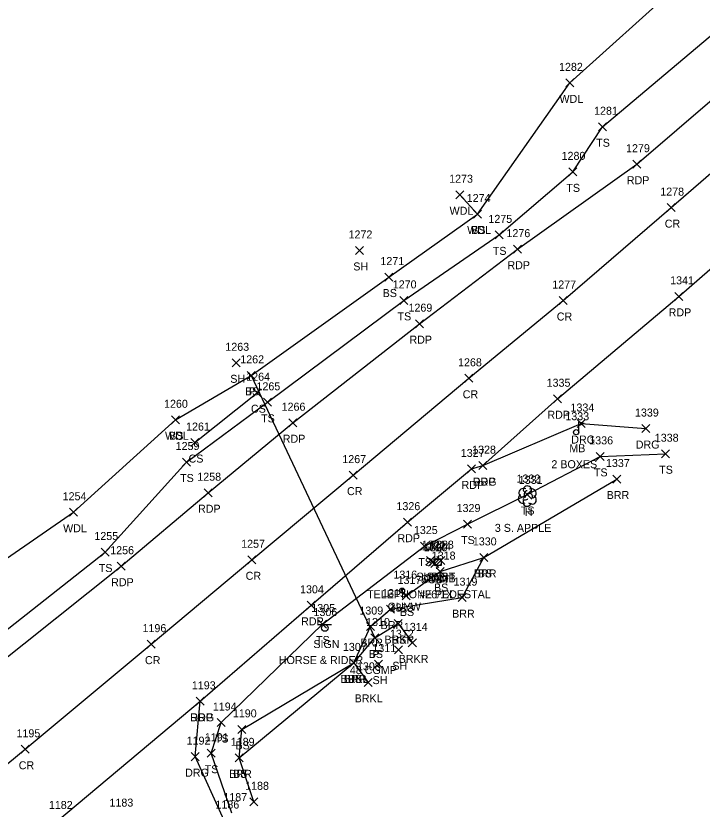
# Model space of a CAD drawing. Extents: x 1611797 to 1633212, y 298978 to 305475.
# Drawn here: x 1612409.8 to 1612581.3, y 300612.3 to 300810.6 of the extents above; entities that cross this region are included whole.
import ezdxf

# ---------------------------------------------------------------- set-up
doc = ezdxf.new("R2010")
doc.units = 0
for name, color, linetype in [('D_A', 7, 'Continuous'), ('D_I', 7, 'Continuous'), ('D_TIC', 7, 'Continuous'), ('DCP', 7, 'Continuous'), ('L_A', 7, 'Continuous'), ('L_C', 7, 'Continuous'), ('L_I', 7, 'Continuous'), ('L_TIC', 7, 'Continuous'), ('LABL', 7, 'Continuous'), ('LAWA', 7, 'Continuous'), ('LAWE', 7, 'Continuous'), ('LELB', 7, 'Continuous'), ('LMB', 7, 'Continuous'), ('LTD', 7, 'Continuous'), ('P_A', 7, 'Continuous'), ('P_I', 7, 'Continuous'), ('P_TIC', 7, 'Continuous'), ('PET', 7, 'Continuous'), ('PRC', 7, 'Continuous'), ('R_A', 7, 'Continuous'), ('R_I', 7, 'Continuous'), ('R_TIC', 7, 'Continuous'), ('RDG', 7, 'Continuous'), ('S_A', 7, 'Continuous'), ('S_C', 7, 'Continuous'), ('S_I', 7, 'Continuous'), ('SSGN', 7, 'Continuous'), ('U_A', 7, 'Continuous'), ('U_C', 7, 'Continuous'), ('U_I', 7, 'Continuous'), ('U_TIC', 7, 'Continuous'), ('UDEFAULT', 7, 'Continuous'), ('UP', 7, 'Continuous'), ('UPGW', 7, 'Continuous')]:
    doc.layers.add(name, color=color, linetype=linetype)

msp = doc.modelspace()

# ---------------------------------------------------------------- linework, layer by layer
at = {"layer": 'D_TIC'}
for points in [[(1612467.58, 300719.73), (1612469.58, 300721.73)], [(1612469.58, 300719.73), (1612467.58, 300721.73)], [(1612498.5, 300654.1), (1612500.5, 300656.1)], [(1612500.5, 300654.1), (1612498.5, 300656.1)]]:
    msp.add_lwpolyline(points, dxfattribs=at)
at = {"layer": 'DCP'}
msp.add_lwpolyline([(1612468.58, 300720.73), (1612499.5, 300655.1)], dxfattribs=at)
at = {"layer": 'L_TIC'}
for points in [[(1612547.19, 300792.82), (1612549.19, 300794.82)], [(1612549.19, 300792.82), (1612547.19, 300794.82)], [(1612555.39, 300781.85), (1612557.39, 300783.85)], [(1612557.39, 300781.85), (1612555.39, 300783.85)], [(1612547.92, 300770.58), (1612549.92, 300772.58)], [(1612549.92, 300770.58), (1612547.92, 300772.58)], [(1612519.74, 300764.86), (1612521.74, 300766.86)], [(1612521.74, 300764.86), (1612519.74, 300766.86)], [(1612524.12, 300760.04), (1612526.12, 300762.04)], [(1612526.12, 300760.04), (1612524.12, 300762.04)], [(1612524.12, 300760.04), (1612526.12, 300762.04)], [(1612526.12, 300760.04), (1612524.12, 300762.04)], [(1612529.55, 300754.83), (1612531.55, 300756.83)], [(1612531.55, 300754.83), (1612529.55, 300756.83)], [(1612494.6, 300750.94), (1612496.6, 300752.94)], [(1612496.6, 300750.94), (1612494.6, 300752.94)], [(1612501.99, 300744.29), (1612503.99, 300746.29)], [(1612503.99, 300744.29), (1612501.99, 300746.29)], [(1612505.73, 300738.46), (1612507.73, 300740.46)], [(1612507.73, 300738.46), (1612505.73, 300740.46)], [(1612463.85, 300722.86), (1612465.85, 300724.86)], [(1612465.85, 300722.86), (1612463.85, 300724.86)], [(1612467.58, 300719.73), (1612469.58, 300721.73)], [(1612469.58, 300719.73), (1612467.58, 300721.73)], [(1612469.07, 300715.39), (1612471.07, 300717.39)], [(1612471.07, 300715.39), (1612469.07, 300717.39)], [(1612471.63, 300712.99), (1612473.63, 300714.99)], [(1612473.63, 300712.99), (1612471.63, 300714.99)], [(1612448.62, 300708.62), (1612450.62, 300710.62)], [(1612450.62, 300708.62), (1612448.62, 300710.62)], [(1612448.62, 300708.62), (1612450.62, 300710.62)], [(1612450.62, 300708.62), (1612448.62, 300710.62)], [(1612453.48, 300702.93), (1612455.48, 300704.93)], [(1612455.48, 300702.93), (1612453.48, 300704.93)], [(1612571.12, 300700.14), (1612573.12, 300702.14)], [(1612573.12, 300700.14), (1612571.12, 300702.14)], [(1612451.39, 300698.07), (1612453.39, 300700.07)], [(1612453.39, 300698.07), (1612451.39, 300700.07)], [(1612554.81, 300699.48), (1612556.81, 300701.48)], [(1612556.81, 300699.48), (1612554.81, 300701.48)], [(1612558.92, 300693.82), (1612560.92, 300695.82)], [(1612560.92, 300693.82), (1612558.92, 300695.82)], [(1612536.56, 300689.94), (1612538.56, 300691.94)], [(1612538.56, 300689.94), (1612536.56, 300691.94)], [(1612423.14, 300685.52), (1612425.14, 300687.52)], [(1612425.14, 300685.52), (1612423.14, 300687.52)], [(1612521.61, 300682.57), (1612523.61, 300684.57)], [(1612523.61, 300682.57), (1612521.61, 300684.57)], [(1612510.92, 300677.07), (1612512.92, 300679.07)], [(1612512.92, 300677.07), (1612510.92, 300679.07)], [(1612431.07, 300675.58), (1612433.07, 300677.58)], [(1612433.07, 300675.58), (1612431.07, 300677.58)], [(1612525.74, 300674.23), (1612527.74, 300676.23)], [(1612527.74, 300674.23), (1612525.74, 300676.23)], [(1612525.74, 300674.23), (1612527.74, 300676.23)], [(1612527.74, 300674.23), (1612525.74, 300676.23)], [(1612514.81, 300670.69), (1612516.81, 300672.69)], [(1612516.81, 300670.69), (1612514.81, 300672.69)], [(1612506.28, 300664.59), (1612508.28, 300666.59)], [(1612508.28, 300664.59), (1612506.28, 300666.59)], [(1612520.29, 300664.18), (1612522.29, 300666.18)], [(1612522.29, 300664.18), (1612520.29, 300666.18)], [(1612502.42, 300661.31), (1612504.42, 300663.31)], [(1612504.42, 300661.31), (1612502.42, 300663.31)], [(1612485.37, 300657.59), (1612487.37, 300659.59)], [(1612487.37, 300657.59), (1612485.37, 300659.59)], [(1612497.37, 300656.95), (1612499.37, 300658.95)], [(1612499.37, 300656.95), (1612497.37, 300658.95)], [(1612504.29, 300657.7), (1612506.29, 300659.7)], [(1612506.29, 300657.7), (1612504.29, 300659.7)], [(1612504.29, 300657.7), (1612506.29, 300659.7)], [(1612506.29, 300657.7), (1612504.29, 300659.7)], [(1612498.5, 300654.1), (1612500.5, 300656.1)], [(1612500.5, 300654.1), (1612498.5, 300656.1)], [(1612507.84, 300652.87), (1612509.84, 300654.87)], [(1612509.84, 300652.87), (1612507.84, 300654.87)], [(1612504.36, 300651.15), (1612506.36, 300653.15)], [(1612506.36, 300651.15), (1612504.36, 300653.15)], [(1612493.26, 300647.87), (1612495.26, 300649.87)], [(1612495.26, 300647.87), (1612493.26, 300649.87)], [(1612493.26, 300647.87), (1612495.26, 300649.87)], [(1612495.26, 300647.87), (1612493.26, 300649.87)], [(1612493.26, 300647.87), (1612495.26, 300649.87)], [(1612495.26, 300647.87), (1612493.26, 300649.87)], [(1612499.41, 300647.57), (1612501.41, 300649.57)], [(1612501.41, 300647.57), (1612499.41, 300649.57)], [(1612496.77, 300643.01), (1612498.77, 300645.01)], [(1612498.77, 300643.01), (1612496.77, 300645.01)], [(1612460.1, 300632.97), (1612462.1, 300634.97)], [(1612462.1, 300632.97), (1612460.1, 300634.97)], [(1612465.2, 300631.26), (1612467.2, 300633.26)], [(1612467.2, 300631.26), (1612465.2, 300633.26)], [(1612457.54, 300625.31), (1612459.54, 300627.31)], [(1612459.54, 300625.31), (1612457.54, 300627.31)], [(1612464.59, 300624.15), (1612466.59, 300626.15)], [(1612466.59, 300624.15), (1612464.59, 300626.15)], [(1612464.59, 300624.15), (1612466.59, 300626.15)], [(1612466.59, 300624.15), (1612464.59, 300626.15)], [(1612468.19, 300613.16), (1612470.19, 300615.16)], [(1612470.19, 300613.16), (1612468.19, 300615.16)]]:
    msp.add_lwpolyline(points, dxfattribs=at)
at = {"layer": 'LABL'}
msp.add_lwpolyline([(1612465.59, 300625.15), (1612494.26, 300648.87), (1612498.37, 300657.95), (1612503.42, 300662.31), (1612521.29, 300665.18), (1612526.74, 300675.23), (1612559.92, 300694.82)], dxfattribs=at)
at = {"layer": 'LAWA'}
for points in [[(1612520.74, 300765.86), (1612525.12, 300761.04), (1612548.19, 300793.82), (1612575.42, 300818.41), (1612609.49, 300842.97), (1612636.94, 300862.89), (1612662.03, 300884.55), (1612680.8, 300909.05), (1612710.16, 300938.44), (1612744.18, 300967.96), (1612778.07, 300997.71), (1612812.04, 301026.39), (1612840.57, 301055.18), (1612885.5, 301091.31), (1612917.8, 301115.74), (1612945.04, 301143.93), (1612981.93, 301163.73), (1613015.11, 301183.73), (1613044.59, 301208.79), (1613081.48, 301227.19), (1613116.05, 301241.71), (1613152.1, 301256.82)], [(1612288.47, 300592.28), (1612300.28, 300590.66), (1612327.78, 300615.2), (1612364.3, 300640.85), (1612390.63, 300663.41), (1612424.14, 300686.52), (1612449.62, 300709.62)]]:
    msp.add_lwpolyline(points, dxfattribs=at)
at = {"layer": 'LAWE'}
for points in [[(1612505.29, 300658.7), (1612508.84, 300653.87)], [(1612494.26, 300648.87), (1612497.77, 300644.01)]]:
    msp.add_lwpolyline(points, dxfattribs=at)
at = {"layer": 'LELB'}
for points in [[(1612240.66, 300571.13), (1612254.26, 300553.79), (1612263.6, 300549.97), (1612273.85, 300550.9), (1612287.75, 300559.94), (1612310.99, 300578.58), (1612339.08, 300600.45), (1612373.06, 300628.46), (1612400.44, 300651.63), (1612432.07, 300676.58), (1612452.39, 300699.07), (1612472.63, 300713.99), (1612506.73, 300739.46), (1612530.55, 300755.83), (1612548.92, 300771.58), (1612556.39, 300782.85), (1612585.92, 300807.71)], [(1612449.62, 300709.62), (1612468.58, 300720.73), (1612502.99, 300745.29), (1612525.12, 300761.04)], [(1612454.48, 300703.93), (1612470.07, 300716.39)], [(1612463.74, 300611.32), (1612458.54, 300626.31), (1612461.1, 300633.97), (1612486.37, 300658.59), (1612511.92, 300678.07), (1612522.61, 300683.57), (1612537.56, 300690.94), (1612555.81, 300700.48), (1612572.12, 300701.14)], [(1612507.28, 300665.59), (1612515.81, 300671.69), (1612526.74, 300675.23)], [(1612469.19, 300614.16), (1612465.59, 300625.15), (1612466.2, 300632.26), (1612494.26, 300648.87), (1612499.5, 300655.1), (1612505.29, 300658.7)]]:
    msp.add_lwpolyline(points, dxfattribs=at)
at = {"layer": 'LMB'}
for p, q in [((1612550.42, 300709.12), (1612551.72, 300708.74)), ((1612550.43, 300706.53), (1612550.43, 300709.12)), ((1612550.43, 300708.22), (1612551.71, 300708.73)), ((1612549.77, 300706.52), (1612549.77, 300706.52))]:
    msp.add_line(p, q, dxfattribs=at)
msp.add_circle((1612549.77, 300706.52), 0.656, dxfattribs=at)
at = {"layer": 'LTD'}
msp.add_line((1612537.55, 300690.61), (1612537.55, 300690.61), dxfattribs=at)
msp.add_line((1612537.55, 300690.61), (1612537.55, 300690.61), dxfattribs=at)
msp.add_arc((1612537.6, 300692.04), 1.05, 335.5272, 180.9563, dxfattribs=at)
for centre, major_axis, ratio, start_param, end_param in [((1612536.76, 300691.27), (1.21, -0.51), 0.895232, 1.570796, 4.712389), ((1612537.34, 300691.07), (-0.208, -0.792), 0.645439, 3.141593, 6.283185), ((1612538.59, 300691.19), (-1.14, -0.48), 0.949671, 1.570796, 4.712389), ((1612536.47, 300689.9), (0.58, -1.04), 0.959034, 3.141593, 6.283185), ((1612537.09, 300689.86), (-0.625, -0.083), 0.423636, 0, 3.141593), ((1612538.05, 300690.44), (-0.5, 0.667), 0.989748, 3.141593, 6.283185), ((1612538.55, 300689.77), (-1.09, 0.79), 0.841452, 1.570796, 4.712389), ((1612537.55, 300689.11), (0.26, 1.06), 0.942809, 1.570796, 4.712389)]:
    msp.add_ellipse(centre, major_axis=major_axis, ratio=ratio, start_param=start_param, end_param=end_param, dxfattribs=at)
at = {"layer": 'P_TIC'}
for points in [[(1612563.95, 300772.49), (1612565.95, 300774.49)], [(1612565.95, 300772.49), (1612563.95, 300774.49)], [(1612572.49, 300761.64), (1612574.49, 300763.64)], [(1612574.49, 300761.64), (1612572.49, 300763.64)], [(1612534.11, 300751.26), (1612536.11, 300753.26)], [(1612536.11, 300751.26), (1612534.11, 300753.26)], [(1612574.4, 300739.47), (1612576.4, 300741.47)], [(1612576.4, 300739.47), (1612574.4, 300741.47)], [(1612545.51, 300738.43), (1612547.51, 300740.43)], [(1612547.51, 300738.43), (1612545.51, 300740.43)], [(1612509.63, 300732.64), (1612511.63, 300734.64)], [(1612511.63, 300732.64), (1612509.63, 300734.64)], [(1612522, 300718.99), (1612524, 300720.99)], [(1612524, 300718.99), (1612522, 300720.99)], [(1612544.1, 300713.88), (1612546.1, 300715.88)], [(1612546.1, 300713.88), (1612544.1, 300715.88)], [(1612477.96, 300707.89), (1612479.96, 300709.89)], [(1612479.96, 300707.89), (1612477.96, 300709.89)], [(1612522.65, 300696.34), (1612524.65, 300698.34)], [(1612524.65, 300696.34), (1612522.65, 300698.34)], [(1612525.47, 300697.16), (1612527.47, 300699.16)], [(1612527.47, 300697.16), (1612525.47, 300699.16)], [(1612493.08, 300694.8), (1612495.08, 300696.8)], [(1612495.08, 300694.8), (1612493.08, 300696.8)], [(1612456.79, 300690.4), (1612458.79, 300692.4)], [(1612458.79, 300690.4), (1612456.79, 300692.4)], [(1612506.62, 300683.04), (1612508.62, 300685.04)], [(1612508.62, 300683.04), (1612506.62, 300685.04)], [(1612435.08, 300672.03), (1612437.08, 300674.03)], [(1612437.08, 300672.03), (1612435.08, 300674.03)], [(1612467.75, 300673.64), (1612469.75, 300675.64)], [(1612469.75, 300673.64), (1612467.75, 300675.64)], [(1612482.55, 300662.26), (1612484.55, 300664.26)], [(1612484.55, 300662.26), (1612482.55, 300664.26)], [(1612442.59, 300652.56), (1612444.59, 300654.56)], [(1612444.59, 300652.56), (1612442.59, 300654.56)], [(1612454.86, 300638.27), (1612456.86, 300640.27)], [(1612456.86, 300638.27), (1612454.86, 300640.27)], [(1612411.05, 300626.28), (1612413.05, 300628.28)], [(1612413.05, 300626.28), (1612411.05, 300628.28)]]:
    msp.add_lwpolyline(points, dxfattribs=at)
at = {"layer": 'PET'}
for points in [[(1612214.78, 300509.59), (1612242.88, 300523.72), (1612263.52, 300537.09), (1612279.04, 300546.89), (1612290.35, 300554.88), (1612314.98, 300573.85), (1612342.77, 300596.1), (1612376.48, 300624.98), (1612403.4, 300647.08), (1612436.08, 300673.03), (1612457.79, 300691.4), (1612478.96, 300708.89), (1612510.63, 300733.64), (1612535.11, 300752.26), (1612564.95, 300773.49), (1612594.34, 300798.76)], [(1612144.95, 300327.73), (1612141.43, 300356.74), (1612142.46, 300380.41), (1612153.41, 300404.36), (1612159, 300411.36), (1612170.98, 300421.86), (1612190.01, 300435.71), (1612213.13, 300453.01), (1612239.2, 300471.61), (1612262.51, 300487.14), (1612292.31, 300507.99), (1612320.91, 300529.26), (1612358.61, 300558.48), (1612393.41, 300587.37), (1612420.13, 300609.37), (1612455.86, 300639.27), (1612483.55, 300663.26), (1612507.62, 300684.04), (1612523.65, 300697.34), (1612526.47, 300698.16), (1612545.1, 300714.88), (1612575.4, 300740.47), (1612596.8, 300759.03)]]:
    msp.add_lwpolyline(points, dxfattribs=at)
at = {"layer": 'PRC'}
msp.add_lwpolyline([(1612099.15, 300430.71), (1612122.26, 300440.06), (1612137.97, 300446.49), (1612163.3, 300457.28), (1612201.88, 300475.21), (1612233.05, 300491.64), (1612256.74, 300506.56), (1612286.27, 300526.59), (1612308.68, 300543.56), (1612346.26, 300573.25), (1612380.66, 300601.4), (1612412.05, 300627.28), (1612443.59, 300653.56), (1612468.75, 300674.64), (1612494.08, 300695.8), (1612523, 300719.99), (1612546.51, 300739.43), (1612573.49, 300762.64), (1612603.84, 300788.89)], dxfattribs=at)
at = {"layer": 'R_TIC'}
for points in [[(1612550.06, 300707.69), (1612552.06, 300709.69)], [(1612552.06, 300707.69), (1612550.06, 300709.69)], [(1612566.18, 300706.43), (1612568.18, 300708.43)], [(1612568.18, 300706.43), (1612566.18, 300708.43)], [(1612525.47, 300697.16), (1612527.47, 300699.16)], [(1612527.47, 300697.16), (1612525.47, 300699.16)], [(1612454.86, 300638.27), (1612456.86, 300640.27)], [(1612456.86, 300638.27), (1612454.86, 300640.27)], [(1612453.56, 300624.44), (1612455.56, 300626.44)], [(1612455.56, 300624.44), (1612453.56, 300626.44)]]:
    msp.add_lwpolyline(points, dxfattribs=at)
at = {"layer": 'RDG'}
for points in [[(1612526.47, 300698.16), (1612551.06, 300708.69), (1612567.18, 300707.43)], [(1612461.83, 300609.47), (1612454.56, 300625.44), (1612455.86, 300639.27)]]:
    msp.add_lwpolyline(points, dxfattribs=at)
at = {"layer": 'SSGN'}
for p, q in [((1612485.33, 300658.44), (1612488.66, 300658.44)), ((1612486.97, 300657.6), (1612486.97, 300657.6))]:
    msp.add_line(p, q, dxfattribs=at)
msp.add_circle((1612486.97, 300657.6), 0.833, dxfattribs=at)
at = {"layer": 'U_TIC'}
for points in [[(1612512.35, 300673.43), (1612514.35, 300675.43)], [(1612514.35, 300673.43), (1612512.35, 300675.43)], [(1612513.46, 300672.75), (1612515.46, 300674.75)], [(1612515.46, 300672.75), (1612513.46, 300674.75)], [(1612514.95, 300673.43), (1612516.95, 300675.43)], [(1612516.95, 300673.43), (1612514.95, 300675.43)]]:
    msp.add_lwpolyline(points, dxfattribs=at)
at = {"layer": 'UDEFAULT'}
for points in [[(1612512.9, 300673.03), (1612514.9, 300675.03)], [(1612514.9, 300673.03), (1612512.9, 300675.03)]]:
    msp.add_lwpolyline(points, dxfattribs=at)
at = {"layer": 'UP'}
for p, q in [((1612514.42, 300673.17), (1612514.42, 300674.84)), ((1612514.42, 300674.84), (1612516.08, 300674.84)), ((1612515.5, 300675.67), (1612515.25, 300674.84)), ((1612515.25, 300674), (1612515.25, 300674)), ((1612516.08, 300674.84), (1612516.08, 300673.17)), ((1612516.08, 300673.17), (1612514.42, 300673.17)), ((1612515, 300672.34), (1612515.25, 300673.17))]:
    msp.add_line(p, q, dxfattribs=at)
msp.add_circle((1612515.25, 300674), 0.833, dxfattribs=at)
at = {"layer": 'UPGW'}
for radius in [0.625, 0.0833]:
    msp.add_circle((1612506.28, 300666.93), radius, dxfattribs=at)

# ---------------------------------------------------------------- texts
at = {"layer": 'D_A'}
for p in [(1612467.96, 300715.73), (1612498.88, 300650.1)]:
    msp.add_text('P', height=2, dxfattribs=at).set_placement(p)
at = {"layer": 'D_I'}
for s, p in [('1262', (1612465.84, 300723.73)), ('1310', (1612497.29, 300658.1))]:
    msp.add_text(s, height=2, dxfattribs=at).set_placement(p)
at = {"layer": 'L_A'}
for s, p in [('WDL', (1612545.61, 300788.82)), ('TS', (1612554.79, 300777.85)), ('TS', (1612547.33, 300766.58)), ('WDL', (1612518.15, 300760.86)), ('WDL', (1612522.54, 300756.04)), ('BS', (1612523.56, 300756.04)), ('TS', (1612528.95, 300750.83)), ('SH', (1612494.08, 300746.94)), ('BS', (1612501.43, 300740.29)), ('TS', (1612505.14, 300734.46)), ('SH', (1612463.34, 300718.86)), ('BS', (1612467.02, 300715.73)), ('CS', (1612468.51, 300711.39)), ('TS', (1612471.04, 300708.99)), ('WDL', (1612447.04, 300704.62)), ('BS', (1612448.06, 300704.62)), ('MB', (1612548.08, 300701.52)), ('CS', (1612452.92, 300698.93)), ('TS', (1612570.53, 300696.14)), ('TS', (1612450.8, 300694.07)), ('TS', (1612554.22, 300695.48)), ('BRR', (1612557.41, 300689.82)), ('TS', (1612535.97, 300685.94)), ('H', (1612536.98, 300685.61)), ('WDL', (1612421.56, 300681.52)), ('TS', (1612521.02, 300678.57)), ('TS', (1612510.33, 300673.07)), ('TS', (1612430.48, 300671.58)), ('BRR', (1612524.23, 300670.23)), ('BS', (1612525.18, 300670.23)), ('BS', (1612514.25, 300666.69)), ('BS', (1612505.72, 300660.59)), ('BRR', (1612518.78, 300660.18)), ('BRR', (1612500.91, 300657.31)), ('TS', (1612484.78, 300653.59)), ('BRR', (1612495.86, 300652.95)), ('BRKR', (1612501.88, 300653.7)), ('BS', (1612503.73, 300653.7)), ('BS', (1612497.94, 300650.1)), ('BRKR', (1612505.43, 300648.87)), ('SH', (1612503.85, 300647.15)), ('BRKL', (1612490.91, 300643.87)), ('BRR', (1612491.75, 300643.87)), ('BS', (1612492.7, 300643.87)), ('SH', (1612498.9, 300643.57)), ('BRKL', (1612494.42, 300639.01)), ('TS', (1612459.51, 300628.97)), ('BS', (1612464.64, 300627.26)), ('TS', (1612456.95, 300621.31)), ('BRR', (1612463.08, 300620.15)), ('BS', (1612464.03, 300620.15))]:
    msp.add_text(s, height=2, dxfattribs=at).set_placement(p)
at = {"layer": 'L_C'}
for s, p in [('2 BOXES', (1612543.59, 300697.52)), ('3 S. APPLE', (1612529.46, 300681.61)), ('48 CGMP', (1612493.22, 300646.1))]:
    msp.add_text(s, height=2, dxfattribs=at).set_placement(p)
at = {"layer": 'L_I'}
for s, p in [('1282', (1612545.5, 300796.82)), ('1281', (1612554.26, 300785.85)), ('1280', (1612546.14, 300774.58)), ('1273', (1612518.04, 300768.86)), ('1274', (1612522.43, 300764.04)), ('1274', (1612522.43, 300764.04)), ('1275', (1612527.85, 300758.83)), ('1272', (1612492.9, 300754.94)), ('1271', (1612500.86, 300748.29)), ('1270', (1612503.95, 300742.46)), ('1263', (1612462.11, 300726.86)), ('1262', (1612465.84, 300723.73)), ('1264', (1612467.33, 300719.39)), ('1265', (1612469.89, 300716.99)), ('1260', (1612446.79, 300712.62)), ('1260', (1612446.79, 300712.62)), ('1333', (1612547.08, 300709.52)), ('1261', (1612452.3, 300706.93)), ('1336', (1612553.06, 300703.48)), ('1338', (1612569.43, 300704.14)), ('1259', (1612449.69, 300702.07)), ('1337', (1612557.23, 300697.82)), ('1332', (1612534.87, 300693.94)), ('1331', (1612535.43, 300693.61)), ('1254', (1612421.45, 300689.52)), ('1329', (1612519.91, 300686.57)), ('1325', (1612509.23, 300681.07)), ('1255', (1612429.38, 300679.58)), ('1330', (1612523.96, 300678.23)), ('1330', (1612523.96, 300678.23)), ('1318', (1612513.69, 300674.69)), ('1317', (1612505.15, 300668.59)), ('1319', (1612519.15, 300668.18)), ('1315', (1612501.29, 300665.31)), ('1305', (1612483.59, 300661.59)), ('1309', (1612495.6, 300660.95)), ('1313', (1612503.16, 300661.7)), ('1313', (1612503.16, 300661.7)), ('1310', (1612497.29, 300658.1)), ('1314', (1612506.72, 300656.87)), ('1312', (1612503.24, 300655.15)), ('1307', (1612491.49, 300651.87)), ('1307', (1612491.49, 300651.87)), ('1307', (1612491.49, 300651.87)), ('1311', (1612498.85, 300651.57)), ('1308', (1612495, 300647.01)), ('1194', (1612458.98, 300636.97)), ('1190', (1612463.99, 300635.26)), ('1191', (1612456.98, 300629.31)), ('1189', (1612463.46, 300628.15)), ('1189', (1612463.46, 300628.15)), ('1188', (1612467.06, 300617.16)), ('1187', (1612461.61, 300614.32))]:
    msp.add_text(s, height=2, dxfattribs=at).set_placement(p)
at = {"layer": 'P_A'}
for s, p in [('RDP', (1612562.44, 300768.49)), ('CR', (1612571.92, 300757.64)), ('RDP', (1612532.6, 300747.26)), ('RDP', (1612572.89, 300735.47)), ('CR', (1612544.94, 300734.43)), ('RDP', (1612508.12, 300728.64)), ('CR', (1612521.43, 300714.99)), ('RDP', (1612542.58, 300709.88)), ('RDP', (1612476.45, 300703.89)), ('RDP', (1612521.14, 300692.34)), ('RDP', (1612523.96, 300693.16)), ('CR', (1612492.51, 300690.8)), ('RDP', (1612455.28, 300686.4)), ('RDP', (1612505.11, 300679.04)), ('RDP', (1612433.57, 300668.03)), ('CR', (1612467.18, 300669.64)), ('RDP', (1612481.04, 300658.26)), ('CR', (1612442.02, 300648.56)), ('RDP', (1612453.35, 300634.27)), ('CR', (1612410.48, 300622.28))]:
    msp.add_text(s, height=2, dxfattribs=at).set_placement(p)
at = {"layer": 'P_I'}
for s, p in [('1279', (1612562.25, 300776.49)), ('1278', (1612570.8, 300765.64)), ('1276', (1612532.36, 300755.26)), ('1341', (1612573.27, 300743.47)), ('1277', (1612543.82, 300742.43)), ('1269', (1612507.88, 300736.64)), ('1268', (1612520.26, 300722.99)), ('1335', (1612542.4, 300717.88)), ('1266', (1612476.17, 300711.89)), ('1327', (1612520.95, 300700.34)), ('1328', (1612523.78, 300701.16)), ('1267', (1612491.34, 300698.8)), ('1258', (1612455.1, 300694.4)), ('1326', (1612504.87, 300687.04)), ('1256', (1612433.34, 300676.03)), ('1257', (1612466.06, 300677.64)), ('1304', (1612480.78, 300666.26)), ('1196', (1612441.41, 300656.56)), ('1193', (1612453.74, 300642.27)), ('1195', (1612409.92, 300630.28)), ('1182', (1612418.01, 300612.37))]:
    msp.add_text(s, height=2, dxfattribs=at).set_placement(p)
at = {"layer": 'R_A'}
for p in [(1612548.55, 300703.69), (1612564.67, 300702.43), (1612523.96, 300693.16), (1612453.35, 300634.27), (1612452.05, 300620.44)]:
    msp.add_text('DRG', height=2, dxfattribs=at).set_placement(p)
at = {"layer": 'R_I'}
for s, p in [('1334', (1612548.36, 300711.69)), ('1339', (1612564.48, 300710.43)), ('1328', (1612523.78, 300701.16)), ('1193', (1612453.74, 300642.27)), ('1192', (1612452.44, 300628.44)), ('1182', (1612418.01, 300612.37)), ('1183', (1612433.15, 300612.96)), ('1186', (1612459.64, 300612.47))]:
    msp.add_text(s, height=2, dxfattribs=at).set_placement(p)
at = {"layer": 'S_A'}
msp.add_text('SIGN', height=2, dxfattribs=at).set_placement((1612484.11, 300652.58))
at = {"layer": 'S_C'}
msp.add_text('HORSE & RIDER', height=2, dxfattribs=at).set_placement((1612475.48, 300648.58))
at = {"layer": 'S_I'}
msp.add_text('1306', height=2, dxfattribs=at).set_placement((1612484.13, 300660.58))
at = {"layer": 'U_A'}
for s, p in [('SUBE', (1612509.88, 300669.43)), ('SUBT', (1612510.96, 300668.75)), ('UTIL', (1612511.07, 300669.03)), ('COMB', (1612511.63, 300669)), ('SUBT', (1612512.45, 300669.43)), ('GUYW', (1612502.67, 300661.93))]:
    msp.add_text(s, height=2, dxfattribs=at).set_placement(p)
at = {"layer": 'U_C'}
for s, p in [('TELEPHONE PEDESTAL', (1612497.53, 300665.03)), ('#26/1X', (1612510.57, 300665))]:
    msp.add_text(s, height=2, dxfattribs=at).set_placement(p)
at = {"layer": 'U_I'}
for s, p in [('1322', (1612511.21, 300677.03)), ('1321', (1612511.22, 300677.43)), ('1320', (1612511.68, 300676.75)), ('1324', (1612512.56, 300677)), ('1323', (1612513.26, 300677.43)), ('1316', (1612504.1, 300669.93))]:
    msp.add_text(s, height=2, dxfattribs=at).set_placement(p)

doc.saveas('drawing.dxf')
